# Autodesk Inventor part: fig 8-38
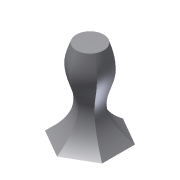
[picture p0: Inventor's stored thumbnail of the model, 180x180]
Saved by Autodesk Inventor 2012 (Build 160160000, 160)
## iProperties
Created: 2007-05
Part Number: fig 8-38
Document SubType Name: Modeling
Designer: Administrator
Density: 1 g/cm^3
Material: Default
Author: Administrator
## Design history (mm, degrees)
sketch "Sketch1"
  geometry: L1 (0, 30)-(25.981, 15); L2 (25.981, 15)-(25.981, -15); L3 (25.981, -15)-(0, -30); L4 (0, -30)-(-25.981, -15); L5 (-25.981, -15)-(-25.981, 15); L6 (-25.981, 15)-(0, 30); 2 further points
  constraints: 12 end point, 1 coincident, 1 vertical, 14 other
workplane "Work Plane1"
sketch "Sketch2"
  geometry: C1 r 12.5 at (0, 0)
  constraints: 1 centre point, 1 other
sketch "Sketch3"
  geometry: L1 (0, 0)-(0, 75)
  constraints: 2 end point, 1 vertical, 1 other
loft "Loft1" sketch "Sketch2", "Sketch3" dims "d5" = 0, "d6" = 90 deg, "d7" = 0, "d8" = 90 deg, "d9" = 0, "d10" = 90 deg, "d11" = 0, "d12" = 0, "d13" = 233.82686, "d14" = 10, "d15" = 75, "d16" = 10, "d17" = 49.08739, "d18" = 10, "d19" = 32.19705, "d20" = 4.29294, "d21" = 35, "d22" = 2.53907, "d23" = 56.85952, "d24" = 7.58127, "d25" = 85, "d26" = 10.45619
body "Solid1"
other parameters: "d1" = 75
